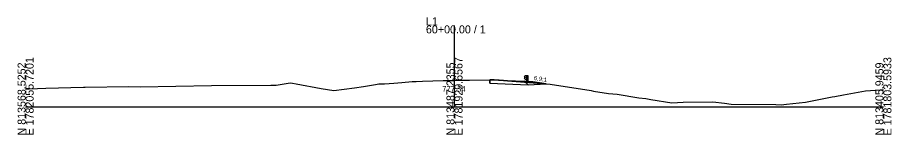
# Model space of a CAD drawing. Extents: x 5574 to 10203, y -10 to 9546.
# Drawn here: x 6597.2 to 6902.8, y 7490.3 to 7531.4 of the extents above; entities that cross this region are included whole.
import ezdxf

# ---------------------------------------------------------------- set-up
doc = ezdxf.new("R2010")
doc.units = 0
for name, color, linetype in [('Exist Cross Section Cell', 7, 'Continuous'), ('Exist XS Center Line Elevation Label', 7, 'Continuous'), ('Exist XS Ground Line', 7, 'Continuous'), ('Prop XS Ditch Slope Text', 7, 'Continuous'), ('Prop XS Earthwork Shape', 7, 'Continuous'), ('Prop XS Finish Grade', 7, 'Continuous'), ('Prop XS Finish Grade Pavement', 7, 'Continuous'), ('Prop XS Guardrail', 7, 'Continuous'), ('Prop XS Pvmt Edge Slope', 7, 'Continuous'), ('Prop XS Subgrade Earthwork', 7, 'Continuous'), ('Scratch_Level_3', 7, 'Continuous'), ('Scratch_Level_6', 7, 'Continuous')]:
    doc.layers.add(name, color=color, linetype=linetype)

msp = doc.modelspace()

# ---------------------------------------------------------------- linework, layer by layer
at = {"layer": 'Exist Cross Section Cell'}
for p, q in [((6750, 7500), (6750, 7528.62)), ((6600, 7500), (6750, 7500)), ((6750, 7500), (6900, 7500))]:
    msp.add_line(p, q, dxfattribs=at)
at = {"layer": 'Exist XS Ground Line'}
for p, q in [((6640.04, 7507.02), (6665.01, 7507.56)), ((6665.01, 7507.56), (6685.74, 7507.68)), ((6685.74, 7507.68), (6687.62, 7507.64)), ((6687.62, 7507.64), (6692.48, 7508.45)), ((6692.48, 7508.45), (6693.36, 7508.3)), ((6693.36, 7508.3), (6694.67, 7508.08)), ((6694.67, 7508.08), (6703.36, 7506.43)), ((6718.12, 7507.18), (6722.35, 7507.86)), ((6722.35, 7507.86), (6723.48, 7508.06)), ((6723.48, 7508.06), (6725.53, 7508.15)), ((6725.53, 7508.15), (6728.83, 7508.3)), ((6728.83, 7508.3), (6731.56, 7508.56)), ((6731.56, 7508.56), (6735.19, 7508.88)), ((6735.19, 7508.88), (6736.57, 7508.95)), ((6736.57, 7508.95), (6738.82, 7509.06)), ((6738.82, 7509.06), (6746.02, 7509.24)), ((6746.02, 7509.24), (6750, 7509.34)), ((6750, 7509.34), (6751.09, 7509.37)), ((6751.09, 7509.37), (6755.24, 7509.43)), ((6755.24, 7509.43), (6762.38, 7509.54)), ((6762.38, 7509.54), (6763.85, 7509.46)), ((6763.85, 7509.46), (6765.67, 7509.37)), ((6765.67, 7509.37), (6780.4, 7508.27)), ((6780.4, 7508.27), (6782.06, 7508.14)), ((6782.06, 7508.14), (6783.5, 7507.96)), ((6783.5, 7507.96), (6797.8, 7505.73)), ((6600, 7506.28), (6601.3, 7506.32)), ((6601.3, 7506.32), (6607.09, 7506.61)), ((6607.09, 7506.61), (6620.19, 7506.97)), ((6620.19, 7506.97), (6620.85, 7506.98)), ((6620.85, 7506.98), (6636.13, 7507.12)), ((6636.13, 7507.12), (6640.04, 7507.02)), ((6703.36, 7506.43), (6707.83, 7505.78)), ((6707.83, 7505.78), (6715.01, 7506.71)), ((6715.01, 7506.71), (6718.12, 7507.18)), ((6797.8, 7505.73), (6798.57, 7505.59)), ((6798.57, 7505.59), (6803.91, 7504.77)), ((6803.91, 7504.77), (6806.94, 7504.46)), ((6886, 7504.24), (6893.76, 7505.66)), ((6893.76, 7505.66), (6898.89, 7505.99)), ((6898.89, 7505.99), (6900, 7506.06)), ((6806.94, 7504.46), (6814.46, 7503.23)), ((6814.46, 7503.23), (6816.91, 7502.91)), ((6816.91, 7502.91), (6818.63, 7502.59)), ((6818.63, 7502.59), (6825.98, 7501.46)), ((6825.98, 7501.46), (6829.99, 7501.63)), ((6829.99, 7501.63), (6840.29, 7501.85)), ((6840.29, 7501.85), (6844.37, 7501.34)), ((6866.06, 7500.97), (6872.77, 7501.67)), ((6872.77, 7501.67), (6882.08, 7503.52)), ((6882.08, 7503.52), (6883.05, 7503.67)), ((6883.05, 7503.67), (6886, 7504.24)), ((6844.37, 7501.34), (6846.77, 7501.02)), ((6846.77, 7501.02), (6862.41, 7500.91)), ((6862.41, 7500.91), (6864.2, 7500.72)), ((6864.2, 7500.72), (6866.06, 7500.97))]:
    msp.add_line(p, q, dxfattribs=at)
at = {"layer": 'Prop XS Earthwork Shape'}
msp.add_lwpolyline([(6775.71, 7507.76), (6782.06, 7508.14), (6780.4, 7508.27), (6765.67, 7509.37), (6763.85, 7509.46), (6762.41, 7509.54), (6762.41, 7508.29)], close=True, dxfattribs=at)
at = {"layer": 'Prop XS Finish Grade'}
for p, q in [((6774.41, 7509.06), (6777.41, 7508.82)), ((6777.41, 7508.82), (6782.06, 7508.14))]:
    msp.add_line(p, q, dxfattribs=at)
at = {"layer": 'Prop XS Finish Grade Pavement'}
msp.add_line((6762.41, 7509.54), (6774.41, 7509.06), dxfattribs=at)
at = {"layer": 'Prop XS Guardrail'}
for p, q in [((6774.44, 7510.73), (6774.41, 7510.67)), ((6774.41, 7510.67), (6774.44, 7510.61)), ((6774.73, 7510.93), (6774.44, 7510.73)), ((6774.44, 7510.61), (6774.73, 7510.41)), ((6775.23, 7510.93), (6774.73, 7510.93)), ((6775.73, 7510.93), (6775.23, 7510.93)), ((6775.23, 7510.93), (6775.23, 7508.43)), ((6775.73, 7508.43), (6775.73, 7510.93)), ((6774.44, 7510.12), (6774.41, 7510.06)), ((6774.41, 7510.06), (6774.44, 7510)), ((6774.73, 7510.32), (6774.44, 7510.12)), ((6774.44, 7510), (6774.73, 7509.8)), ((6774.73, 7510.41), (6774.73, 7510.32)), ((6774.73, 7509.8), (6775.23, 7509.8))]:
    msp.add_line(p, q, dxfattribs=at)
at = {"layer": 'Prop XS Pvmt Edge Slope'}
msp.add_line((6774.41, 7509.06), (6775.71, 7507.76), dxfattribs=at)
at = {"layer": 'Prop XS Subgrade Earthwork'}
for p, q in [((6762.41, 7508.29), (6762.41, 7509.54)), ((6762.41, 7508.29), (6775.71, 7507.76)), ((6775.71, 7507.76), (6782.06, 7508.14))]:
    msp.add_line(p, q, dxfattribs=at)
at = {"layer": 'Scratch_Level_3'}
for p, q in [((6774.41, 7509.06), (6775.71, 7507.76)), ((6777.41, 7508.82), (6774.41, 7509.06)), ((6775.71, 7507.76), (6782.06, 7508.14)), ((6782.06, 7508.14), (6777.41, 7508.82))]:
    msp.add_line(p, q, dxfattribs=at)
at = {"layer": 'Scratch_Level_6'}
msp.add_lwpolyline([(6775.71, 7507.76), (6782.06, 7508.14), (6780.4, 7508.27), (6765.67, 7509.37), (6763.85, 7509.46), (6762.41, 7509.54), (6762.41, 7508.29)], close=True, dxfattribs=at)

# ---------------------------------------------------------------- texts
at = {"layer": 'Exist Cross Section Cell'}
for s, p in [('L1', (6740, 7528.62)), ('60+00.00 / 1', (6740, 7525.82))]:
    msp.add_text(s, height=2.8, dxfattribs=at).set_placement(p)
for s, p in [('E 1782055.7201', (6602.8, 7490)), ('E 1781929.6567', (6752.8, 7490)), ('E 1781803.5933', (6902.8, 7490)), ('N 813568.5252', (6600, 7490)), ('N 813487.2355', (6750, 7490)), ('N 813405.9459', (6900, 7490))]:
    msp.add_text(s, height=2.8, rotation=90, dxfattribs=at).set_placement(p)
at = {"layer": 'Exist XS Center Line Elevation Label'}
msp.add_text('777.34', height=2, dxfattribs=at).set_placement((6745.72, 7505.34))
at = {"layer": 'Prop XS Ditch Slope Text'}
msp.add_text('6.9:1', height=1.5, rotation=350.46, dxfattribs=at).set_placement((6777.67, 7509.51))

doc.saveas('drawing.dxf')
